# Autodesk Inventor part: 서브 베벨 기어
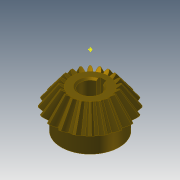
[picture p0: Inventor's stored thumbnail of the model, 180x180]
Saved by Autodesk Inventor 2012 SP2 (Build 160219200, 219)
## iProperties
Created: 2014-10
Part Number: 서브 베벨 기어
Material: Steel, Mild
Document SubType Name: Modeling
Designer: KYOUNG IL JANG
Categories: <?xml version="1.0" encoding="UTF-16"?> <MemberInstance><Categories><FamilyTemplate><FamilyTemplateParameter ValueType="xs:double" Id="1" ObjectReferenceKey="da
Mass: 134.866 g
Surface Area: 63.6518 cm^2
Volume: 17.1585 cm^3
Density: 7.86 g/cm^3
CustomPartVersion: 1
Company: 한국ATC센터
Author: KYOUNG IL JANG
Revision Number: 1
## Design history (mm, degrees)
node "맨 위 점"
node "메쉬 평면2"
sketch "톱니 본체 스케치"
  geometry: L1 (0, 0)-(18.003, -31.331); L2 (18.003, -31.331)-(21.664, -28.891); L3 (21.664, -28.891)-(0, 0); L4 (20, -30)-(0, 0); L5 (10.813, -18.818)-(13.012, -17.352); L6 (18.003, -31.331)-(10.813, -18.818); L7 (21.664, -28.891)-(13.012, -17.352); L8 (0, -39.387)-(0, 6.564) reference; L9 (0, -30)-(21.664, -30)
  constraints: 16 end point, 4 point on line, 3 perpendicular, 2 collinear, 1 horizontal alignment, 1 vertical alignment
  dimensions: "d0" = 40 diameter of L4.start L8 (= da_de); "d1" = 36.00616 diameter of L1.end L8 (= da_dfe); "d2" = 43.3282 diameter of L2.end L8 (= da_dae); "d3" = 14.4 distance between parallel lines of L2 L5 (= da_b); "d4" = 28.8906 vertical distance of L2.end L1.start (= da_ve)
revolve "톱니 본체" sketch "톱니 본체 스케치" stored, may be unused: angle "d5" = 90 deg
node "시작점"
node "톱니 평면"
sketch "시작 스케치"
  geometry: L1 (0, -23.505)-(0, 10.645) reference; L2 (-0.834, -2.928)-(0.834, -2.928); A1 r 8.898 centre (-9.698, -3.713) between (-0.834, -2.928) and (-3.903, 3.04); A2 r 8.898 centre (9.698, -3.713) between (3.903, 3.04) and (0.834, -2.928); A3 r 27.357 centre (0, -24.037) between (3.903, 3.04) and (-3.903, 3.04); 1 further point
  constraints: 6 point on circle, 3 centre point, 3 symmetric about line, 2 end point, 1 coincident, 1 perpendicular, 1 other
  dimensions: "d7" = 8.89846 radius of A1 (= fd_rr); "d8" = 9.69794 horizontal distance of point (0, -24.037) A1.centre (= fd_x); "d9" = 20.32439 vertical distance of point (0, -24.037) A1.centre (= fd_y); "d57" = 27.35701 radius of A3 (= 0.5 x fd_dva + 0.3 x da_he); "d58" = 21.10901 distance from line of A3.centre L2 (= 0.5 x fd_dva - 1.12 x da_he)
node "끝점"
  node "끝 평면"
sketch "3D 스케치 오른쪽"
  node "Helical Curve Right" dims "d65" = 229.90621 (computed from da_dm, da_delta, da_beta), "d66" = 31.5, "d67" = 40 (= da_de), "d68" = -5.88003 (= -da_delta), "d69" = 12.16458 (computed from fd_loft, da_delta)
node "끝 평면 오른쪽"
sketch "끝 스케치 오른쪽"
  geometry: L1 (0, -22.649)-(0, 12.15) reference; L2 (-0.497, -1.72)-(0.497, -1.72); A1 r 5.299 centre (-5.775, -2.187) between (-0.497, -1.72) and (-2.324, 1.834); A2 r 5.299 centre (5.775, -2.187) between (2.324, 1.834) and (0.497, -1.72); A3 r 16.291 centre (0, -14.29) between (2.324, 1.834) and (-2.324, 1.834); 1 further point
  constraints: 6 point on circle, 3 centre point, 3 symmetric about line, 2 end point, 1 coincident, 1 perpendicular, 1 other
  dimensions: "d70" = 5.77526 horizontal distance of A3.centre A1.centre (computed from fd_x, fd_ratio); "d71" = 12.10346 vertical distance of point (0, -14.29) A1.centre (computed from fd_y, fd_ratio); "d72" = 5.29916 radius of A1 (computed from fd_rr, fd_ratio); "d73" = 12.57071 distance from line of point (0, -14.29) L2 (computed from d58, fd_ratio); "d74" = 16.29149 radius of A3 (computed from d57, fd_ratio)
feature "로프트 오른쪽" sketch "끝 스케치 오른쪽" dims "d75" = 0, "d77" = 0, "d79" = 0, "d80" = 90 deg, "d85" = 20, "d92" = 90 deg, "d93" = 90 deg, "da_teethtype" = 0 [user parameter]
sketch "3D 스케치 왼쪽"
  node "Helical Curve Left" dims "d26" = 229.90621 (computed from da_dm, da_delta, da_beta), "d27" = 12.16458 (computed from fd_loft, da_delta), "d28" = 40 (= da_de), "d29" = -5.88003 (= -da_delta)
node "끝 평면 왼쪽"
sketch "끝 스케치 왼쪽" dims "d56" = 10.82768 (derived)
  geometry: L1 (0, -35.087)-(0, 18.089) reference; L2 (-0.497, -1.716)-(0.497, -1.716); A1 r 5.299 centre (-5.775, -2.183) between (-0.497, -1.716) and (-2.324, 1.838); A2 r 5.299 centre (5.775, -2.183) between (2.324, 1.838) and (0.497, -1.716); A3 r 16.291 centre (0, -14.287) between (2.324, 1.838) and (-2.324, 1.838); 2 further points; 1 other entity
  constraints: 6 point on circle, 3 centre point, 3 symmetric about line, 2 end point, 1 coincident, 2 other
  dimensions: "d30" = 5.29916 radius of A1 (computed from fd_rr, fd_ratio); "d31" = 5.77526 horizontal distance of point (0, -14.287) A1.centre (computed from fd_x, fd_ratio); "d32" = 12.10346 vertical distance of A1.centre point (0, -14.287) (computed from fd_y, fd_ratio); "d61" = 16.29149 radius of A3 (computed from d57, fd_ratio); "d62" = 12.57071 distance from line of point (0, -14.287) L2 (computed from d58, fd_ratio)
feature "로프트 왼쪽" sketch "끝 스케치 왼쪽" dims "d35" = 0, "d37" = 0, "d39" = 0, "d40" = 90 deg, "d84" = 10, "d90" = 90 deg, "d91" = 90 deg, "da_teethtype" = 0 [user parameter]
sketch "본체 스케치"
  geometry: L1 (0, -35.038)-(0, -19.531) reference; L2 (18.003, -31.331)-(10.813, -18.818) reference; L3 (10.813, -18.818)-(0, -18.818); L4 (18.003, -31.331)-(0, -31.331)
  constraints: 4 end point, 2 perpendicular, 2 point on line
revolve "본체 고정" sketch "본체 스케치" stored, may be unused: angle "d46" = 90 deg
sketch "Sketch6"
  geometry: L1 (20, -30)-(0, 0) reference; L2 (0, -37.8)-(0, 6.3) reference
feature "피치 지름" sketch "Sketch6" dims angle "d47" = 90 deg
sketch "스케치8"
  geometry: C1 r 17 at (0, 0); 1 further point
  constraints: 1 centre point, 1 coincident
  dimensions: "d94" = 34 diameter of C1
extrude "돌출1" join sketch "스케치8" distance "d95" = 10; taper "d96" = 0 deg
sketch "스케치9"
  geometry: 1 further point
hole "구멍1" sketch "스케치9" at (0, 0) diameter "d97" = 12; stored, may be unused: countersink angle "d101" = 90 deg, drill point angle "d103" = 118 deg; dims "d98" = 6, "d99" = 4, "d100" = 2, "d102" = 8
sketch "스케치10"
  geometry: 1 further point
sketch "스케치11"
  geometry: 1 further point
sketch "스케치12"
  geometry: L1 (-2, 5.657)-(-2, 7.8); L2 (-2, 7.8)-(2, 7.8); L3 (2, 7.8)-(2, 5.657); A1 r 6 centre (0, 0) between (-2, 5.657) and (2, 5.657) reference; 1 further point
  constraints: 6 end point, 2 parallel, 2 point on circle, 1 perpendicular, 1 vertical
  dimensions: "d104" = 4 distance of L1.end L2.end; "d105" = 13.8 dimension on A1 L2
extrude "돌출2" cut sketch "스케치12" stored distance "d106" = 7; taper "d107" = 0 deg
chamfer "모따기1" distance "d108" = 1; stored, may be unused: second distance "d109" = 2, angle "d110" = 45 deg
body "Solid1"
feature "로프트" dims "d17" = 0, "d18" = 90 deg, "d19" = 0, "d20" = 90 deg, "d89" = 0, "da_teethtype" = 0 [user parameter]
pattern_circular "원형 패턴" dims angle "d22" = 360 deg, "d88" = 0, "da_teethtype" = 0 [user parameter]
pattern_circular "원형 패턴 오른쪽" dims angle "d82" = 360 deg, "da_teethtype" = 0 [user parameter]
pattern_circular "원형 패턴 왼쪽" dims angle "d42" = 360 deg, "da_teethtype" = 0 [user parameter]
sketch "끝 스케치"
  geometry: L1 (0, -15.359)-(0, 6.983) reference; L2 (-0.497, -1.72)-(0.497, -1.72); A1 r 5.299 centre (-5.775, -2.187) between (-0.497, -1.72) and (-2.324, 1.834); A2 r 5.299 centre (5.775, -2.187) between (2.324, 1.834) and (0.497, -1.72); A3 r 16.291 centre (0, -14.29) between (2.324, 1.834) and (-2.324, 1.834); 1 further point
  constraints: 6 point on circle, 3 centre point, 3 symmetric about line, 2 end point, 1 coincident, 1 other
  dimensions: "d12" = 5.29916 radius of A1 (computed from fd_rr, fd_ratio); "d15" = 5.77526 horizontal distance of A1.centre point (0, -14.29) (computed from fd_x, fd_ratio); "d16" = 12.10346 vertical distance of A1.centre point (0, -14.29) (computed from fd_y, fd_ratio); "d59" = 16.29149 radius of A3 (computed from d57, fd_ratio); "d60" = 12.57071 distance from line of A3.centre L2 (computed from d58, fd_ratio)
body "Srf1"
other parameters: "da_b" = 14.4 [user parameter; used in 2 equation terms], "da_de" = 40 [user parameter; used in 4 equation terms], "da_dae" = 43.3282 [user parameter; used in 2 equation terms], "da_dfe" = 36.00616 [user parameter; used in 1 equation term], "da_le" = 36.05551 [user parameter; used in 1 equation term], "da_omega" = 90 deg [user parameter; used in 1 equation term], "da_beta" = 0 [user parameter; used in 2 equation terms], "da_delta" = 5.88003 [user parameter; used in 8 equation terms], "da_alpha" = 20 deg [user parameter; used in 2 equation terms], "da_he" = 4.4 [user parameter; used in 4 equation terms], "da_ve" = 28.8906 [user parameter; used in 1 equation term], "fd_dv" = 48.07402 (computed from da_de, da_delta) [user parameter; used in 1 equation term], "fd_dva" = 52.07402 (computed from da_dae, da_delta) [user parameter; used in 3 equation terms], "fd_dvb" = 45.1748 (computed from fd_dv, da_alpha) [user parameter; used in 2 equation terms], "da_zv" = 240.37008 [user parameter; used in 1 equation term], "fd_loft" = 14.62 (= da_b + 0.05 x da_he) [user parameter; used in 4 equation terms], "fd_ratio" = 5.95514 (computed from da_le, fd_loft) [user parameter; used in 15 equation terms], "fd_rr" = 8.89846 (computed from fd_dd, fd_dvb) [user parameter; used in 6 equation terms], "fd_angle" = 0.66075 (computed from da_zv) [user parameter; used in 4 equation terms], "fd_x1" = 1.58709 (computed from da_dvw, fd_angle) [user parameter; used in 1 equation term], "fd_y1" = 23.98456 (computed from da_dvw, fd_angle) [user parameter; used in 1 equation term], "fd_x2" = 8.11084 (computed from fd_rr, fd_angle2, fd_angle) [user parameter; used in 1 equation term], "fd_y2" = 3.66016 (computed from fd_rr, fd_angle2, fd_angle) [user parameter; used in 1 equation term], "fd_x" = 9.69794 (= fd_x1 + fd_x2) [user parameter; used in 4 equation terms], "fd_y" = 20.32439 (= fd_y1 - fd_y2) [user parameter; used in 4 equation terms], "fd_angle2" = 3.57832 (computed from fd_dvb, fd_dd, da_alpha) [user parameter; used in 2 equation terms], "fd_dd" = 48.55402 (= fd_dva - 0.8 x da_he) [user parameter; used in 2 equation terms], "da_dvw" = 48.07402 [user parameter; used in 2 equation terms], "d11" = 14.62 (= fd_loft), "da_dm" = 32.01232 [user parameter; used in 2 equation terms], "da_x" = 0 [user parameter], "da_m" = 2 [user parameter], "d48" = 0, "d49" = 0, "d50" = 90 deg (= da_omega), "d51" = 9 deg (computed from da_z), "d52" = 0, "d53" = 0, "d54" = 0
